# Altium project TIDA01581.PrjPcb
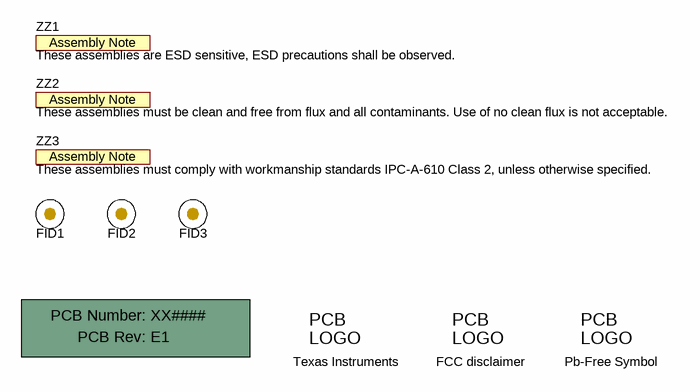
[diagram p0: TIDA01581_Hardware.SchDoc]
CopyrightYear: 2016; PCB_Layout: Garrett Satterfield; PCB_Rev: E1; PRJ_Customer: Public Release; PRJ_Engineer: Garrett Satterfield; PRJ_Number: XX####; PRJ_Title: TIDA-01581; SCH_Rev: E1; TechSupport: http://www.ti.com/support; TID: N/A
3 sheets, 135 parts. Net scope: flat (ports and power ports of the same name join across sheets).
Board file: TIDA01581.PcbDoc
Sheets:
  TIDA01581_Hardware.SchDoc
  TIDA01581_1.SchDoc
  TIDA01581_2.SchDoc

## Sheet TIDA01581_Hardware.SchDoc: Hardware
size 431 x 279 mm; Date: Not shown in title block; ApprovedBy: Not shown in title block; CheckedBy: Not shown in title block; Author: Not shown in title block; CompanyName: Not shown in title block; Engineer: Not shown in title block; Organization: Not shown in title block; Address1: Not shown in title block; Address2: Not shown in title block; Address3: Not shown in title block; Address4: Not shown in title block; DocumentNumber: 1; Revision: Use project parameter SCH_Rev; SheetNumber: 2; SheetTotal: 2; PageSetup: Record=PageOptions¦CenterHorizontal=True¦CenterVertical=True¦PrintScale=1.00¦XCorrection=1.00¦YCorrection=1.00¦PrintKind=0¦BorderSize=5000000¦LeftOffset=0¦BottomOffset=0¦Orientation=2¦PaperLength=1000¦PaperWidth=1000¦Scale=100¦PaperSource=15¦PrintQuality=600¦MediaType=1¦DitherType=10¦PaperKind=Letter¦PrintScaleMode=1

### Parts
!PCB1  Printed Circuit Board  (value not drawn)  (mechanical)
FID1  Fiducial  [Fiducial10-20]  (value not drawn)
FID2  Fiducial  [Fiducial10-20]  (value not drawn)
FID3  Fiducial  [Fiducial10-20]  (value not drawn)
Logo1  Texas Instruments  [TI_Stacked_Overlay_Small]  (no BOM)
Logo2  FCC disclaimer  [FCC_disclaimer]  (no BOM)
Logo3  Pb-Free Symbol  [Pb-Free_Overlay_Small]  (no BOM)
ZZ1  These assemblies are ESD sensitive, ESD precautions shall be observed.  [AssemblyNote]  (no BOM)
ZZ2  These assemblies must be clean and free from flux and all contaminants. Use of no clean flux is not acceptable.  [AssemblyNote]  (no BOM)
ZZ3  These assemblies must comply with workmanship standards IPC-A-610 Class 2, unless otherwise specified.  [AssemblyNote]  (no BOM)

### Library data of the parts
!PCB1 = PCB: Manufacturer: Any; PartNumber: XX####; SymbolCreator: a0412235
FID1-FID3 = Fiducial: Fiducial mark.  There is nothing to buy or mount.; SymbolCreator: codlsc
Logo1 = TI_Logo: Texas Instrument Corporate Signature; SymbolCreator: codlsc
Logo2 = FCC_disclaimer: SymbolCreator: a0412235
Logo3 = Pb-Free: SymbolCreator: a0412235
ZZ1-ZZ3 = AssemblyNote: SymbolCreator: codlsc

## Sheet TIDA01581_1.SchDoc: Boost LED Driver
size 431 x 279 mm; Date: Not shown in title block; ApprovedBy: Not shown in title block; CheckedBy: Not shown in title block; Author: Not shown in title block; CompanyName: Not shown in title block; DrawnBy: Garrett Satterfield; Engineer: Not shown in title block; Organization: Not shown in title block; Address1: Not shown in title block; Address2: Not shown in title block; Address3: Not shown in title block; Address4: Not shown in title block; DocumentNumber: 1; Revision: Use project parameter SCH_Rev; SheetNumber: 1; SheetTotal: 2; PageSetup: Record=PageOptions¦CenterHorizontal=True¦CenterVertical=True¦PrintScale=0.64¦XCorrection=1.00¦YCorrection=1.00¦PrintKind=0¦BorderSize=5000000¦LeftOffset=0¦BottomOffset=0¦Orientation=2¦PaperLength=1000¦PaperWidth=1000¦Scale=100¦PaperSource=15¦PrintQuality=-3¦MediaType=1¦DitherType=10¦PrintScaleMode=1¦PaperKind=Letter¦PaperIndex=1
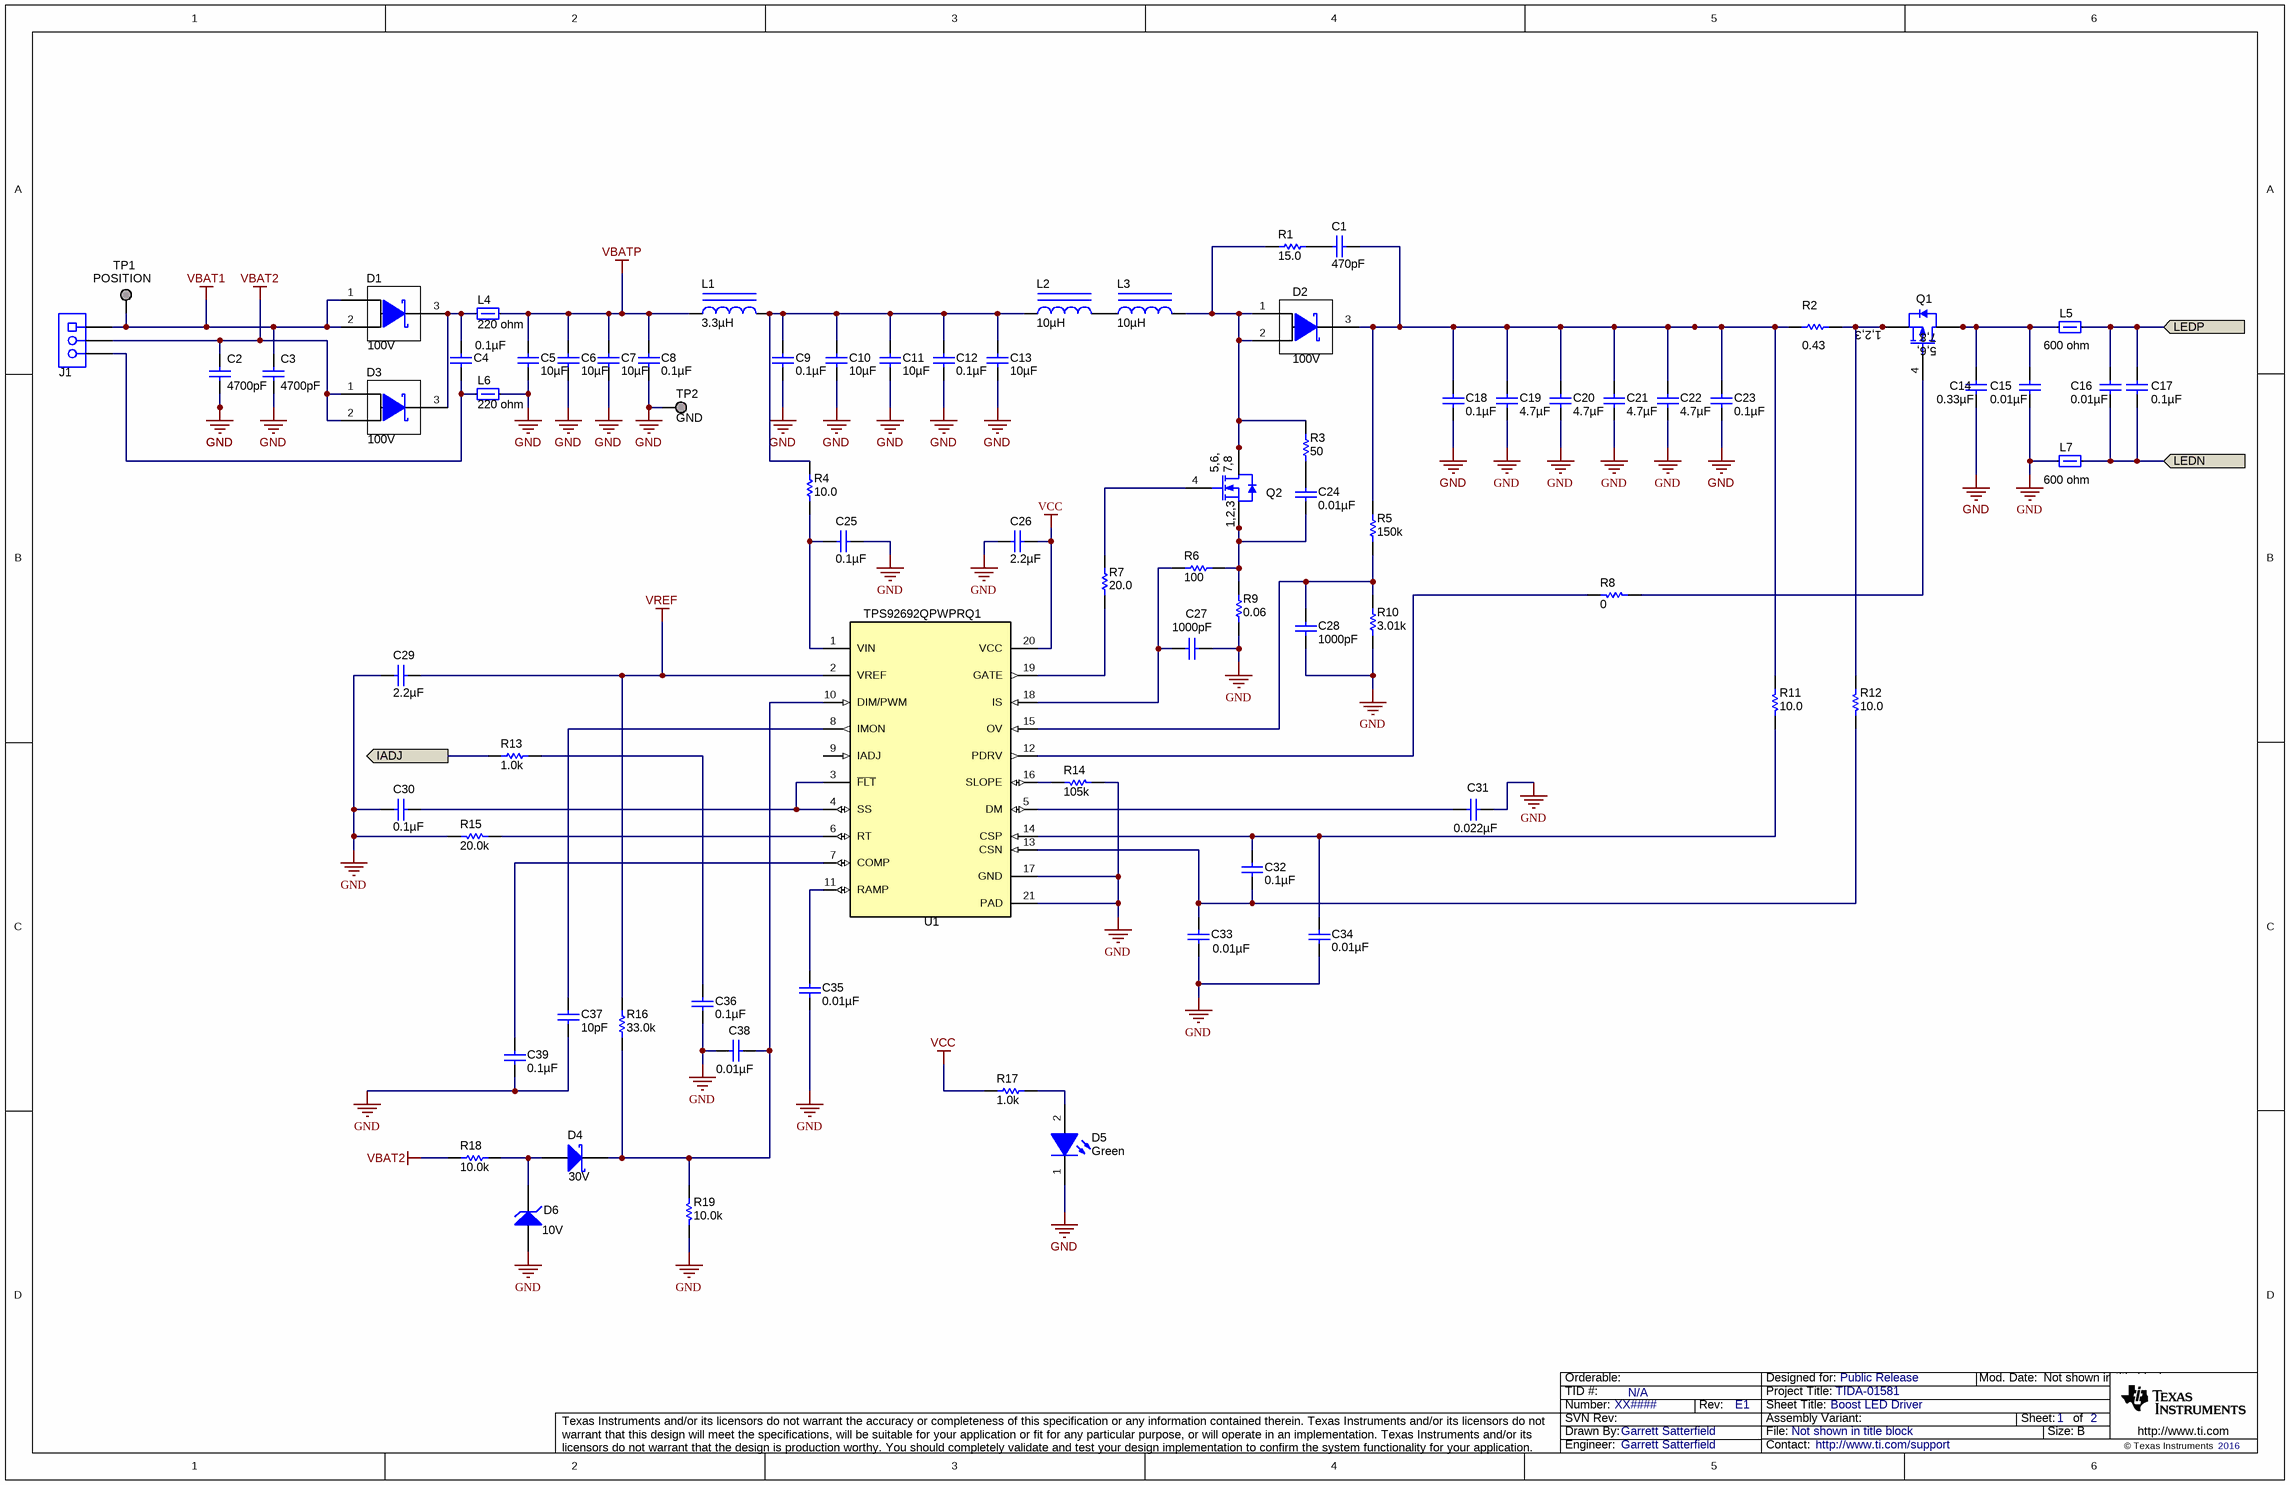
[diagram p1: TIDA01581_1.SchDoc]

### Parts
C1  ValueDisplayed: 470pF  [0603]  (hidden comment: GRM188R72A471KA01D)
C2  ValueDisplayed: 4700pF  [0603_HV]  (hidden comment: CGA3E2X7R2A472K080AA)
C3  ValueDisplayed: 4700pF  [0603_HV]  (hidden comment: CGA3E2X7R2A472K080AA)
C4  ValueDisplayed: 0.1µF  [0603_HV]  (hidden comment: CGA3E2X7R1H104K080AA)
C5  ValueDisplayed: 10µF  [1210_280]  (hidden comment: CGA6P3X7S1H106K250AB)
C6  ValueDisplayed: 10µF  [1210_280]  (hidden comment: CGA6P3X7S1H106K250AB)
C7  ValueDisplayed: 10µF  [1210_280]  (hidden comment: CGA6P3X7S1H106K250AB)
C8  ValueDisplayed: 0.1µF  [0603_HV]  (hidden comment: CGA3E2X7R1H104K080AA)
C9  ValueDisplayed: 0.1µF  [0603_HV]  (hidden comment: CGA3E2X7R1H104K080AA)
C10  ValueDisplayed: 10µF  [1210_280]  (hidden comment: CGA6P3X7S1H106K250AB)
C11  ValueDisplayed: 10µF  [1210_280]  (hidden comment: CGA6P3X7S1H106K250AB)
C12  ValueDisplayed: 0.1µF  [0603_HV]  (hidden comment: CGA3E2X7R1H104K080AA)
C13  ValueDisplayed: 10µF  [1210_280]  (hidden comment: CGA6P3X7S1H106K250AB)
C14  ValueDisplayed: 0.33µF  [0805_HV]  (hidden comment: C2012X7S2A334K125AB)
C15  ValueDisplayed: 0.01µF  [0603]  (hidden comment: CGA3E2X7R2A103K080AA)
C16  ValueDisplayed: 0.01µF  [0603_HV]  (hidden comment: CGA3E2X7R2A103K080AA)
C17  ValueDisplayed: 0.1µF  [0603_HV]  (hidden comment: CGA3E2X7R1H104K080AA)
C18  ValueDisplayed: 0.1µF  [0603_HV]  (hidden comment: CGA3E2X7R1H104K080AA)
C19  ValueDisplayed: 4.7µF  [1210_220]  (hidden comment: CGA6M3X7S2A475K200AB)
C20  ValueDisplayed: 4.7µF  [1210_220]  (hidden comment: CGA6M3X7S2A475K200AB)
C21  ValueDisplayed: 4.7µF  [1210_220]  (hidden comment: CGA6M3X7S2A475K200AB)
C22  ValueDisplayed: 4.7µF  [1210_220]  (hidden comment: CGA6M3X7S2A475K200AB)
C23  ValueDisplayed: 0.1µF  [0603_HV]  (hidden comment: CGA3E2X7R1H104K080AA)
C24  ValueDisplayed: 0.01µF  [0603]  (hidden comment: 06031C103MAT2A)
C25  ValueDisplayed: 0.1µF  [0805_HV]  (hidden comment: C2012X7R2A104K125AA)
C26  ValueDisplayed: 2.2µF  [0805_HV]  (hidden comment: CGA4J3X7R1E225K125AB)
C27  ValueDisplayed: 1000pF  [0603_HV]  (hidden comment: CGA3E2X7R2A102K080AA)
C28  ValueDisplayed: 1000pF  [0603]  (hidden comment: CGA3E2X7R2A102K080AA)
C29  ValueDisplayed: 2.2µF  [0805_HV]  (hidden comment: CGA4J3X7R1E225K125AB)
C30  ValueDisplayed: 0.1µF  [1206_180]  (hidden comment: CGA5L2X7R2A104K160AA)
C31  ValueDisplayed: 0.022µF  [0603_HV]  (hidden comment: CGA3E2X7R2A223K080AA)
C32  ValueDisplayed: 0.1µF  [1206_180]  (hidden comment: CGA5L2X7R2A104K160AA)
C33  ValueDisplayed: 0.01µF  [0603]  (hidden comment: CGA3E2X7R2A103K080AA)
C34  ValueDisplayed: 0.01µF  [0603_HV]  (hidden comment: CGA3E2X7R2A103K080AA)
C35  ValueDisplayed: 0.01µF  [0603]  (hidden comment: CGA3E2X7R2A103K080AA)
C36  ValueDisplayed: 0.1µF  [1206_180]  (hidden comment: CGA5L2X7R2A104K160AA)
C37  ValueDisplayed: 10pF  [0603_HV]  (hidden comment: CGA3E2C0G1H100D080AA)
C38  ValueDisplayed: 0.01µF  [0603_HV]  (hidden comment: CGA3E2X7R2A103K080AA)
C39  ValueDisplayed: 0.1µF  [0805_HV]  (hidden comment: CEU4J2X7R1H104K125AE)
D1  value 100V  [TO-277A]  (hidden comment: V12P10-M3/86A)
D2  value 100V  [PowerDI5]  (hidden comment: PDS3100Q-13)
D3  value 100V  [TO-277A]  (hidden comment: V12P10-M3/86A)
D4  value 30V  [SOD-123]  (hidden comment: BAT42W-7-F)
D5  value Green  [WL-SMCW_GREEN]  (hidden comment: 150060VS75000)
D6  value 10V  [SOD-123]  (hidden comment: MMSZ5240B-7-F)
J1  1727023  [Phoenix_1727023]  (value not drawn)
L1  ValueDisplayed: 3.3µH  [CLF7045]  (hidden comment: CLF7045T-3R3N)
L2  ValueDisplayed: 10µH  [IHLP-2525BD]  (hidden comment: IHLP2525BDER100M01)
L3  ValueDisplayed: 10µH  [IHLP-2525BD]  (hidden comment: IHLP2525BDER100M01)
L4  value 220 ohm  [1206]  (hidden comment: FBMH3216HM221NTV)
L5  value 600 ohm  [1206]  (hidden comment: MI1206K601R-10)
L6  value 220 ohm  [1206]  (hidden comment: FBMH3216HM221NTV)
L7  value 600 ohm  [1206]  (hidden comment: MI1206K601R-10)
Q1  SI7415DN-T1-GE3  [PowerPAK_1212-8]  (value not drawn)
Q2  STL8N10LF3  [PowerFLAT5x6_R]  (value not drawn)
R1  ValueDisplayed: 15.0  [0603]  (hidden comment: CRCW060315R0FKEA)
R2  0.43  [1206]
R3  ValueDisplayed: 50  [0603]  (hidden comment: CRCW060350R0FKEA)
R4  ValueDisplayed: 10.0  [1206]  (hidden comment: CRCW120610R0FKEA)
R5  ValueDisplayed: 150k  [0603_HV]  (hidden comment: CRCW0603150KFKEA)
R6  ValueDisplayed: 100  [0603_HV]  (hidden comment: CRCW0603100RFKEA)
R7  ValueDisplayed: 20.0  [0603]  (hidden comment: CRCW060320R0FKEA)
R8  ValueDisplayed: 0  [0603_HV]  (hidden comment: CRCW06030000Z0EA)
R9  ValueDisplayed: 0.06  [2010]  (hidden comment: CSRN2010FK60L0)
R10  ValueDisplayed: 3.01k  [0603_HV]  (hidden comment: CRCW06033K01FKEA)
R11  ValueDisplayed: 10.0  [0603_HV]  (hidden comment: CRCW060310R0FKEA)
R12  ValueDisplayed: 10.0  [0603_HV]  (hidden comment: CRCW060310R0FKEA)
R13  ValueDisplayed: 1.0k  [0603]  (hidden comment: CRCW06031K00JNEA)
R14  ValueDisplayed: 105k  [0603_HV]  (hidden comment: CRCW0603105KFKEA)
R15  ValueDisplayed: 20.0k  [0603_HV]  (hidden comment: CRCW060320K0FKEA)
R16  ValueDisplayed: 33.0k  [0603]  (hidden comment: CRCW060333K0FKEA)
R17  ValueDisplayed: 1.0k  [0603]  (hidden comment: CRCW06031K00JNEA)
R18  ValueDisplayed: 10.0k  [0603_HV]  (hidden comment: CRCW060310K0FKEA)
R19  ValueDisplayed: 10.0k  [0603]  (hidden comment: CRCW060310K0FKEA)
TP1  POSITION  [Keystone1502-2]
TP2  GND  [Keystone1502-2]
U1  TPS92692QPWPRQ1  [PWP0020D_N]

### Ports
IADJ, LEDN, LEDP

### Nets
GND: C2.2 C3.2 C5.2 C6.2 C7.2 C8.2 C9.2 C10.2 C11.2 C12.2 C13.2 C14.2 C15.2 C18.2 C19.1 C20.1 C21.1 C22.1 C23.2 C25.1 C26.2 C27.2 C28.2 C29.1 C30.1 C31.1 C33.2 C34.2 C35.2 C36.2 C37.2 C38.2 C39.1 D5.1(K) D6.2(A) L6.2 L7.1 R9.1 R10.1 R14.1 R15.2 R19.1 TP2.1 U1.17(GND) U1.21(PAD)
VBAT1: C3.1 D1.1(A) D1.2(A) J1.1 TP1.1
VBAT2: C2.1 D3.1(A) D3.2(A) J1.2 R18.2
VBATP: C5.1 C6.1 C7.1 C8.1 L1.1 L4.2
VCC: C26.1 R17.1 U1.20(VCC)
VREF: C29.2 R16.1 U1.2(VREF)
IADJ: R13.1 ; port IADJ
LEDN: C16.1 C17.2 L7.2 ; port LEDN
LEDP: C16.2 C17.1 L5.2 ; port LEDP
NetC1_1: C1.1 C18.1 C19.2 C20.2 C21.2 C22.2 C23.1 D2.3(K) R2.1 R5.2 R11.2
NetC1_2: C1.2 R1.2
NetC4_1: C4.1 D1.3(K) D3.3(K) L4.1
NetC4_2: C4.2 J1.3 L6.1
NetC9_1: C9.1 C10.1 C11.1 C12.1 C13.1 L1.2 L2.1 R4.2
NetC14_1: C14.1 C15.1 L5.1 Q1.5(D) Q1.6(D) Q1.7(D) Q1.8(D) Q1.9(D)
NetC24_1: C24.1 R3.1
NetC24_2: C24.2 Q2.1(S) Q2.2(S) Q2.3(S) R6.2 R9.2
NetC25_2: C25.2 R4.1 U1.1(VIN)
NetC27_1: C27.1 R6.1 U1.18(IS)
NetC28_1: C28.1 R5.1 R10.2 U1.15(OV)
NetC30_2: C30.2 U1.3(~{FLT}) U1.4(SS)
NetC31_2: C31.2 U1.5(DM)
NetC32_1: C32.1 C34.1 R11.1 U1.14(CSP)
NetC32_2: C32.2 C33.1 R12.1 U1.13(CSN)
NetC35_1: C35.1 U1.11(RAMP)
NetC36_1: C36.1 R13.2
NetC37_1: C37.1 U1.8(IMON)
NetC38_1: C38.1 D4.1(K) R16.2 R19.2 U1.10(DIM/PWM)
NetC39_2: C39.2 U1.7(COMP)
NetD2_1: D2.1(A) D2.2(A) L3.2 Q2.5(D) Q2.6(D) Q2.7(D) Q2.8(D) Q2.9(D) R1.1 R3.2
NetD4_2: D4.2(A) D6.1(K) R18.1
NetD5_2: D5.2(A) R17.2
NetL2_2: L2.2 L3.1
NetQ1_1: Q1.1(S) Q1.2(S) Q1.3(S) R2.2 R12.2
NetQ1_4: Q1.4(G) R8.1
NetQ2_4: Q2.4(G) R7.2
NetR7_1: R7.1 U1.19(GATE)
NetR8_2: R8.2 U1.12(PDRV)
NetR14_2: R14.2 U1.16(SLOPE)
NetR15_1: R15.1 U1.6(RT)

Not connected (* = marked no-connect by the designer): U1 9(IADJ)

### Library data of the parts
C1 = GRM188R72A471KA01D: CAP, CERM, 470 pF, 100 V, +/- 10%, X7R, 0603; Manufacturer: MuRata; Polarized: N; CompType: Capacitor; Value: 470pF; U/M: EA; Cap_F: 0.00000000047; Tolerance_%: 10; Value1: Unknown; VDC_V: 100; Value2: 100V; TaMin_C: -55; TaMax_C: 125; SizeArea_mm2: 1.28; SizeAreaWB_mm2: 4.68; SizeX_mm: 1.6; SizeY_mm: 0.8; SizeZ_mm: 1; AEC Category: Q200
C2 C3 = CGA3E2X7R2A472K080AA: CAP, CERM, 4700 pF, 100 V, +/- 10%, X7R, AEC-Q200 Grade 1, 0603; Manufacturer: TDK; Polarized: N; CompType: Capacitor; Value: 4700pF; U/M: EA; Cap_F: 0.0000000047; Tolerance_%: 10; ESR_ohm: 0.469862; Value1: 0.469862 ohm; VDC_V: 100; Value2: 100V; IRMS_A: 0.32335; TaMin_C: -55; TaMax_C: 125; Cap_Case: 0603; SizeArea_mm2: 1.28; SizeAreaWB_mm2: 4.68; SizeX_mm: 1.6; SizeY_mm: 0.8; SizeZ_mm: 1; AEC Category: Q200; AEC Qualified: Y
C4 C8 C9 C12 C17 C18 C23 = CGA3E2X7R1H104K080AA: CAP, CERM, 0.1 µF, 50 V, +/- 10%, X7R, AEC-Q200 Grade 1, 0603; Manufacturer: TDK; Polarized: N; CompType: Capacitor; Value: 0.1uF; U/M: EA; Cap_F: 0.0000001; Tolerance_%: 10; ESR_ohm: 0.0296; Value1: 0.0296 ohm; VDC_V: 50; Value2: 50V; IRMS_A: 0.97199; TaMin_C: -55; TaMax_C: 125; Cap_Case: 0603; SizeArea_mm2: 1.28; SizeAreaWB_mm2: 4.68; SizeX_mm: 1.6; SizeY_mm: 0.8; SizeZ_mm: 1; AEC Category: Q200; AEC Qualified: Y
C5-C7 C10 C11 C13 = CGA6P3X7S1H106K250AB: CAP, CERM, 10 µF, 50 V, +/- 10%, X7S, AEC-Q200 Grade 1, 1210; Manufacturer: TDK; Polarized: N; CompType: Capacitor; Value: 10uF; U/M: EA; Cap_F: 0.00001; Tolerance_%: 10; ESR_ohm: 0.002827; Value1: 0.002827 ohm; VDC_V: 50; Value2: 50V; IRMS_A: 4.37286; TaMin_C: -55; TaMax_C: 125; SizeArea_mm2: 8; SizeAreaWB_mm2: 14.7; SizeX_mm: 3.2; SizeY_mm: 2.5; SizeZ_mm: 2.8; AEC Category: Q200; AEC Qualified: Y; AEC Grade: 1
C14 = C2012X7S2A334K125AB: CAP, CERM, 0.33 µF, 100 V, +/- 10%, X7S, 0805; Manufacturer: TDK; Polarized: N; CompType: Capacitor; Value: 0.33uF; U/M: EA; Cap_F: 0.00000033; Tolerance_%: 10; ESR_ohm: 0.019477; Value1: 0.019477 ohm; VDC_V: 100; Value2: 100V; IRMS_A: 1.48561; TaMin_C: -55; TaMax_C: 125; Cap_Case: 0805; SizeArea_mm2: 2.5; SizeAreaWB_mm2: 6.75; SizeX_mm: 2; SizeY_mm: 1.25; SizeZ_mm: 1.45; AEC Category: Q200
C15 C33 C35 = CGA3E2X7R2A103K080AA: CAP, CERM, 0.01 µF, 100 V, +/- 10%, X7R, AEC-Q200 Grade 1, 0603; Manufacturer: TDK; Polarized: N; CompType: Capacitor; Value: 0.01uF; U/M: EA; Cap_F: 0.00000001; Tolerance_%: 10; ESR_ohm: 0.235428; Value1: 0.235428 ohm; VDC_V: 100; Value2: 100V; IRMS_A: 0.396995; TaMin_C: -55; TaMax_C: 125; SizeArea_mm2: 1.28; SizeAreaWB_mm2: 4.68; SizeX_mm: 1.6; SizeY_mm: 0.8; SizeZ_mm: 1; AEC Category: Q200; AEC Qualified: Y
C16 C34 C38 = CGA3E2X7R2A103K080AA: CAP, CERM, 0.01 µF, 100 V, +/- 10%, X7R, AEC-Q200 Grade 1, 0603; Manufacturer: TDK; Polarized: N; CompType: Capacitor; Value: 0.01uF; U/M: EA; Cap_F: 0.00000001; Tolerance_%: 10; ESR_ohm: 0.235428; Value1: 0.235428 ohm; VDC_V: 100; Value2: 100V; IRMS_A: 0.396995; TaMin_C: -55; TaMax_C: 125; Cap_Case: 0603; SizeArea_mm2: 1.28; SizeAreaWB_mm2: 4.68; SizeX_mm: 1.6; SizeY_mm: 0.8; SizeZ_mm: 1; AEC Category: Q200; AEC Qualified: Y
C19-C22 = CGA6M3X7S2A475K200AB: CAP, CERM, 4.7 µF, 100 V, +/- 10%, X7S, AEC-Q200 Grade 1, 1210; Manufacturer: TDK; Polarized: N; CompType: Capacitor; Value: 4.7uF; U/M: EA; Cap_F: 0.0000047; Tolerance_%: 10; ESR_ohm: 0.004236; Value1: 0.004236 ohm; VDC_V: 100; Value2: 100V; IRMS_A: 3.57337; TaMin_C: -55; TaMax_C: 125; SizeArea_mm2: 8; SizeAreaWB_mm2: 14.7; SizeX_mm: 3.2; SizeY_mm: 2.5; SizeZ_mm: 2.2; AEC Category: Q200; AEC Qualified: Y; AEC Grade: 1
C24 = 06031C103MAT2A: CAP, CERM, 0.01 µF, 100 V, +/- 20%, X7R, 0603; Manufacturer: AVX; Polarized: N; CompType: Capacitor; Value: 0.01uF; U/M: EA; Cap_F: 0.00000001; Tolerance_%: 20; ESR_ohm: 0.098; Value1: 0.098 ohm; VDC_V: 100; Value2: 100V; TaMin_C: -55; TaMax_C: 125; SizeArea_mm2: 1.28; SizeAreaWB_mm2: 4.68; SizeX_mm: 1.6; SizeY_mm: 0.8; SizeZ_mm: 1; AEC Category: Q200
C25 = C2012X7R2A104K125AA: CAP, CERM, 0.1 µF, 100 V, +/- 10%, X7R, 0805; Manufacturer: TDK; Polarized: N; CompType: Capacitor; Value: 0.1uF; U/M: EA; Cap_F: 0.0000001; Tolerance_%: 10; ESR_ohm: 0.0158; Value1: 0.0158 ohm; VDC_V: 100; Value2: 100V; TaMin_C: -55; TaMax_C: 125; Cap_Case: 0805; AEC Category: Q200
C26 C29 = CGA4J3X7R1E225K125AB: CAP, CERM, 2.2 µF, 25 V, +/- 10%, X7R, AEC-Q200 Grade 1, 0805; Manufacturer: TDK; Polarized: N; CompType: Capacitor; Value: 2.2uF; U/M: EA; Cap_F: 0.0000022; Tolerance_%: 10; Value1: Unknown; VDC_V: 25; Value2: 25V; TaMin_C: -55; TaMax_C: 125; Cap_Case: 0805; SizeArea_mm2: 2.5; SizeAreaWB_mm2: 6.75; SizeX_mm: 2; SizeY_mm: 1.25; SizeZ_mm: 1.45; AEC Category: Q200; AEC Qualified: Y; AEC Grade: 1
C27 = CGA3E2X7R2A102K080AA: CAP, CERM, 1000 pF, 100 V, +/- 10%, X7R, AEC-Q200 Grade 1, 0603; Manufacturer: TDK; Polarized: N; CompType: Capacitor; Value: 1000pF; U/M: EA; Cap_F: 0.000000001; Tolerance_%: 10; ESR_ohm: 1.97137; Value1: 1.97137 ohm; VDC_V: 100; Value2: 100V; IRMS_A: 0.305705; TaMin_C: -55; TaMax_C: 125; Cap_Case: 0603; SizeArea_mm2: 1.28; SizeAreaWB_mm2: 4.68; SizeX_mm: 1.6; SizeY_mm: 0.8; SizeZ_mm: 1; AEC Category: Q200; AEC Qualified: Y
C28 = CGA3E2X7R2A102K080AA: CAP, CERM, 1000 pF, 100 V, +/- 10%, X7R, AEC-Q200 Grade 1, 0603; Manufacturer: TDK; Polarized: N; CompType: Capacitor; Value: 1000pF; U/M: EA; Cap_F: 0.000000001; Tolerance_%: 10; ESR_ohm: 1.97137; Value1: 1.97137 ohm; VDC_V: 100; Value2: 100V; IRMS_A: 0.305705; TaMin_C: -55; TaMax_C: 125; SizeArea_mm2: 1.28; SizeAreaWB_mm2: 4.68; SizeX_mm: 1.6; SizeY_mm: 0.8; SizeZ_mm: 1; AEC Category: Q200; AEC Qualified: Y
C30 C32 C36 = CGA5L2X7R2A104K160AA: CAP, CERM, 0.1 µF, 100 V, +/- 10%, X7R, AEC-Q200 Grade 1, 1206; Manufacturer: TDK; Polarized: N; CompType: Capacitor; Value: 0.1uF; U/M: EA; Cap_F: 0.0000001; Tolerance_%: 10; ESR_ohm: 0.030343; Value1: 0.030343 ohm; VDC_V: 100; Value2: 100V; IRMS_A: 1.33802; TaMin_C: -55; TaMax_C: 125; SizeArea_mm2: 5.12; SizeAreaWB_mm2: 10.92; SizeX_mm: 3.2; SizeY_mm: 1.6; SizeZ_mm: 1.8; AEC Category: Q200; AEC Qualified: Y; AEC Grade: 1
C31 = CGA3E2X7R2A223K080AA: CAP, CERM, 0.022 µF, 100 V, +/- 10%, X7R, AEC-Q200 Grade 1, 0603; Manufacturer: TDK; Polarized: N; CompType: Capacitor; Value: 0.022uF; U/M: EA; Cap_F: 0.000000022; Tolerance_%: 10; ESR_ohm: 0.083542; Value1: 0.083542 ohm; VDC_V: 100; Value2: 100V; IRMS_A: 0.609312; TaMin_C: -55; TaMax_C: 125; Cap_Case: 0603; SizeArea_mm2: 1.28; SizeAreaWB_mm2: 4.68; SizeX_mm: 1.6; SizeY_mm: 0.8; SizeZ_mm: 1; AEC Category: Q200; AEC Qualified: Y
C37 = CGA3E2C0G1H100D080AA: CAP, CERM, 10 pF, 50 V, +/- 5%, C0G/NP0, AEC-Q200 Grade 1, 0603; Manufacturer: TDK; Polarized: N; CompType: Capacitor; Value: 10pF; U/M: EA; Cap_F: 0.00000000001; Tolerance_%: 5; Value1: Unknown; VDC_V: 50; Value2: 50V; TaMin_C: -55; TaMax_C: 125; Cap_Case: 0603; SizeArea_mm2: 1.28; SizeAreaWB_mm2: 4.68; SizeX_mm: 1.6; SizeY_mm: 0.8; SizeZ_mm: 1; AEC Category: Q200; AEC Qualified: Y
C39 = CEU4J2X7R1H104K125AE: CAP, CERM, 0.1 µF, 50 V, +/- 10%, X7R, AEC-Q200 Grade 1, 0805; Manufacturer: TDK; Polarized: N; CompType: Capacitor; Value: 0.1uF; U/M: EA; Cap_F: 0.0000001; Tolerance_%: 10; Value1: Unknown; VDC_V: 50; Value2: 50V; TaMin_C: -55; TaMax_C: 125; Cap_Case: 0805; SizeArea_mm2: 2.5; SizeAreaWB_mm2: 6.75; SizeX_mm: 2; SizeY_mm: 1.25; SizeZ_mm: 1.5; AEC Category: Q200; AEC Qualified: Y; AEC Grade: 1
D1 D3 = V12P10-M3/86A: Diode, Schottky, 100 V, 12 A, AEC-Q101, TO-277A; Manufacturer: Vishay-Semiconductor; U/M: EA; Vf_V: 0.7; Value1: 12A; Value2: 0.7V; Io_A: 12; Vr_V: 100; TJmax_C: 150; SizeAreaWB_mm2: 56.1; SizeArea_mm2: 29.9; SizeX_mm: 4.6; SizeY_mm: 6.5; SizeZ_mm: 1.2; AEC Category: Q101; AEC Qualified: Y
D2 = PDS3100Q-13: Diode, Schottky, 100 V, 3 A, AEC-Q101, PowerDI5; Manufacturer: Diodes Inc.; U/M: EA; Vf_V: 0.76; Value1: 3A; Value2: 0.76V; Io_A: 3; Vr_V: 100; TJmax_C: 150; AEC Category: Q101; AEC Qualified: Y
D4 = BAT42W-7-F: Diode, Schottky, 30 V, 0.2 A, SOD-123; Manufacturer: Diodes Inc.; U/M: EA; Vf_V: 1; Value1: 0.2A; Value2: 1V; Io_A: 0.2; Vr_V: 30; AEC Category: Q101
D5 = 150060VS75000: LED, Green, SMD; Manufacturer: Wurth Elektronik; Type: AlInGaP; Vf_V: 2; Value2: 2V; Io_A: 0.02; Value1: W; U/M: EA
D6 = MMSZ5240B-7-F: Diode, Zener, 10 V, 500 mW, SOD-123; Manufacturer: Diodes Inc.; SymbolCreator: a0412235; U/M: EA; Power_W: 0.5; Vz_V: 10; Value1: 0.5W; RJA_CperW: 350; SizeAreaWB_mm2: 13.095; SizeArea_mm2: 6.545; SizeX_mm: 3.85; SizeY_mm: 1.7; SizeZ_mm: 1.35; AEC Category: Q101
J1 = 1727023: Terminal Block Receptacle, 3x1, 3.81mm, R/A, TH; Manufacturer: Phoenix Contact; SymbolCreator: a0412235
L1 = CLF7045T-3R3N: Inductor, Shielded, Ferrite, 3.3 µH, 5 A, 0.0213 ohm, SMD; Manufacturer: TDK; Value: 3.3uH; Ind_H: 3.3E-6; Imax_A: 5; Irms: 4.1A @ 30C rise; Isat: 5A @ 10% inductance drop; DCR_ohm: 0.0213; Value2: 5A; SizeAreaWB_mm2: 85.54; SizeArea_mm2: 52.54; SizeX_mm: 7.4; SizeY_mm: 7.1; SizeZ_mm: 4.8; AEC Category: Q200
L2 L3 = IHLP2525BDER100M01: Inductor, Shielded, Powdered Iron, 10 µH, 2.5 A, 0.129 ohm, SMD; Manufacturer: Vishay-Dale; Value: 10uH; Ind_H: 10.0E-6; Imax_A: 2.5; Irms: 2.5A @ 40C rise; Isat: 7A @ 20% inductance drop; DCR_ohm: 0.129; Value2: 2.5A; SizeAreaWB_mm2: 75.0442; SizeArea_mm2: 44.3842; SizeX_mm: 6.86; SizeY_mm: 6.47; SizeZ_mm: 2.4; AEC Category: Q200
L4 L6 = FBMH3216HM221NTV: Ferrite Bead, 220 ohm @ 100 MHz, 4 A, 1206; Manufacturer: Taiyo Yuden; Imax_A: 4; DCR_ohm: 0.02; Value1: 0.02 ohm; Value2: 4A; SizeAreaWB_mm2: 10.92; SizeArea_mm2: 5.12; SizeX_mm: 3.2; SizeY_mm: 1.6; SizeZ_mm: 1.35; ZTyp@100MHz_Ohm: 220
L5 L7 = MI1206K601R-10: Ferrite Bead, 600 ohm @ 100 MHz, 1.5 A, 1206; Manufacturer: Laird-Signal Integrity Products; Imax_A: 1.5; DCR_ohm: 0.08; Value1: 0.08 ohm; Value2: 1.5A; ZTyp@100MHz_Ohm: 600; Ztyp@1GHz_Ohm: 130
Q1 = SI7415DN-T1-GE3: MOSFET, P-CH, -60 V, -3.6 A, PowerPAK 1212; Manufacturer: Vishay-Siliconix; Alternate Manufacturer: None; U/M: EA; ChType: P; Value: -60V; Value1: 0.11 ohm; Rdson45_ohm: 0.11; Value2: 15 nC; QgTyp_nC: 15; Vgs_V: 20
Q2 = STL8N10LF3: MOSFET, N-CH, 100 V, 20 A, AEC-Q101, 8-PowerVDFN; Manufacturer: STMicroelectronics; Alternate Manufacturer: None; U/M: EA; ChType: N; Value: 100V; VdsMax_V: 100; Value1: ? ohm; Value2: 20.5 nC; QgTyp_nC: 20.5; Vgs_V: 20; AEC Category: Q101; AEC Qualified: Y
R1 = CRCW060315R0FKEA: RES, 15.0, 1%, 0.1 W, 0603; Manufacturer: Vishay-Dale; CompType: Resistor; Value: 15.0; Res_ohm: 15; Value_Code: 15R0; Tolerance_%: 1; Power_W: 0.1; Value2: 0.1W; VDC_V: 75; TempCo: 100 ppm/C; SizeArea_mm2: 1.28; SizeX_mm: 1.6; SizeY_mm: 0.8; EIA_Code: E96; U/M: EA; AEC Category: Q200
R2 = CMP-0078337-1: RES, 0.43, 1%, 0.5 W, 1206
R3 = CRCW060350R0FKEA: RES, 50, 1%, 0.1 W, 0603; Manufacturer: Vishay-Dale; CompType: Resistor; Value: 50; Value_Code: 50R0; Tolerance_%: 1; Power_W: 0.1; Value2: 0.1W; VDC_V: 75; TempCo: 100 ppm/C; SizeArea_mm2: 1.28; SizeX_mm: 1.6; SizeY_mm: 0.8; U/M: EA; AEC Category: Q200
R4 = CRCW120610R0FKEA: RES, 10.0, 1%, 0.25 W, 1206; Manufacturer: Vishay-Dale; CompType: Resistor; Value: 10.0; Res_ohm: 10; Value_Code: 10R0; Tolerance_%: 1; Power_W: 0.25; Value2: 0.25W; VDC_V: 200; TempCo: 100 ppm/C; EIA_Code: E96; U/M: EA
R5 = CRCW0603150KFKEA: RES, 150 k, 1%, 0.1 W, 0603; Manufacturer: Vishay-Dale; CompType: Resistor; Value: 150k; Res_ohm: 150000; Tolerance_%: 1; Power_W: 0.1; Value2: 0.1W; VDC_V: 75; TempCo: 100 ppm/C; SizeArea_mm2: 1.28; SizeX_mm: 1.6; SizeY_mm: 0.8; EIA_Code: E96; U/M: EA; AEC Category: Q200
R6 = CRCW0603100RFKEA: RES, 100, 1%, 0.1 W, 0603; Manufacturer: Vishay-Dale; CompType: Resistor; Value: 100; Value_Code: 100R; Tolerance_%: 1; Power_W: 0.1; Value2: 0.1W; VDC_V: 75; TempCo: 100 ppm/C; EIA_Code: E96; U/M: EA; AEC Category: Q200
R7 = CRCW060320R0FKEA: RES, 20.0, 1%, 0.1 W, 0603; Manufacturer: Vishay-Dale; CompType: Resistor; Value: 20.0; Res_ohm: 20; Value_Code: 20R0; Tolerance_%: 1; Power_W: 0.1; Value2: 0.1W; VDC_V: 75; TempCo: 100 ppm/C; SizeArea_mm2: 1.28; SizeX_mm: 1.6; SizeY_mm: 0.8; EIA_Code: E96; U/M: EA; AEC Category: Q200
R8 = CRCW06030000Z0EA: RES, 0, 5%, 0.1 W, 0603; Manufacturer: Vishay-Dale; CompType: Resistor; Value: 0; Value_Code: 0000; Tolerance_%: 5; Power_W: 0.1; Value2: 0.1W; VDC_V: 75; TempCo: 200 ppm/C; EIA_Code: E24; U/M: EA; SizeArea_mm2: 1.28; SizeX_mm: 1.6; SizeY_mm: 0.8; SizeZ_mm: 1; AEC Category: Q200
R9 = CSRN2010FK60L0: RES, 0.06, 1%, 1 W, 2010; Manufacturer: Stackpole Electronics Inc; CompType: Resistor; Value: 0.06; Value_Code: R060; Tolerance_%: 1; Value2: 1W; TempCo: 250 ppm/C; SizeArea_mm2: 12.5; SizeX_mm: 5; SizeY_mm: 2.5; SizeZ_mm: 1.66; U/M: EA; AEC Category: Q200
R10 = CRCW06033K01FKEA: RES, 3.01 k, 1%, 0.1 W, 0603; Manufacturer: Vishay-Dale; CompType: Resistor; Value: 3.01k; Res_ohm: 3010; Value_Code: 3k01; Tolerance_%: 1; Power_W: 0.1; Value2: 0.1W; VDC_V: 75; TempCo: 100 ppm/C; SizeArea_mm2: 1.28; SizeX_mm: 1.6; SizeY_mm: 0.8; EIA_Code: E96; U/M: EA; AEC Category: Q200
R11 R12 = CRCW060310R0FKEA: RES, 10.0, 1%, 0.1 W, 0603; Manufacturer: Vishay-Dale; CompType: Resistor; Value: 10.0; Res_ohm: 10; Value_Code: 10R0; Tolerance_%: 1; Power_W: 0.1; Value2: 0.1W; VDC_V: 75; TempCo: 100 ppm/C; EIA_Code: E96; U/M: EA
R13 R17 = CRCW06031K00JNEA: RES, 1.0 k, 5%, 0.1 W, 0603; Manufacturer: Vishay-Dale; CompType: Resistor; Value: 1.0k; Res_ohm: 1000; Value_Code: 1k00; Tolerance_%: 5; Power_W: 0.1; Value2: 0.1W; VDC_V: 75; TempCo: 200 ppm/C; SizeArea_mm2: 1.28; SizeX_mm: 1.6; SizeY_mm: 0.8; SizeZ_mm: 1; EIA_Code: E24; U/M: EA; AEC Category: Q200
R14 = CRCW0603105KFKEA: RES, 105 k, 1%, 0.1 W, 0603; Manufacturer: Vishay-Dale; CompType: Resistor; Value: 105k; Res_ohm: 105000; Tolerance_%: 1; Power_W: 0.1; Value2: 0.1W; VDC_V: 75; TempCo: 100 ppm/C; SizeArea_mm2: 1.28; SizeX_mm: 1.6; SizeY_mm: 0.8; EIA_Code: E96; U/M: EA; AEC Category: Q200
R15 = CRCW060320K0FKEA: RES, 20.0 k, 1%, 0.1 W, 0603; Manufacturer: Vishay-Dale; CompType: Resistor; Value: 20.0k; Res_ohm: 20000; Value_Code: 20k0; Tolerance_%: 1; Power_W: 0.1; Value2: 0.1W; VDC_V: 75; TempCo: 100 ppm/C; SizeArea_mm2: 1.28; SizeX_mm: 1.6; SizeY_mm: 0.8; EIA_Code: E96; U/M: EA; AEC Category: Q200
R16 = CRCW060333K0FKEA: RES, 33.0 k, 1%, 0.1 W, 0603; Manufacturer: Vishay-Dale; CompType: Resistor; Value: 33.0k; Res_ohm: 33000; Value_Code: 33k0; Tolerance_%: 1; Power_W: 0.1; Value2: 0.1W; VDC_V: 75; TempCo: 100 ppm/C; U/M: EA; SizeArea_mm2: 1.28; SizeX_mm: 1.6; SizeY_mm: 0.8; AEC Category: Q200
R18 = CRCW060310K0FKEA: RES, 10.0 k, 1%, 0.1 W, 0603; Manufacturer: Vishay-Dale; CompType: Resistor; Value: 10.0k; Res_ohm: 10000; Value_Code: 10k0; Tolerance_%: 1; Power_W: 0.1; Value2: 0.1W; VDC_V: 75; TempCo: 100 ppm/C; EIA_Code: E96; U/M: EA
R19 = CRCW060310K0FKEA: RES, 10.0 k, 1%, 0.1 W, 0603; Manufacturer: Vishay-Dale; CompType: Resistor; Value: 10.0k; Res_ohm: 10000; Value_Code: 10k0; Tolerance_%: 1; Power_W: 0.1; Value2: 0.1W; VDC_V: 75; TempCo: 100 ppm/C; EIA_Code: E96; U/M: EA; AEC Category: Q200; SizeArea_mm2: 1.28; SizeX_mm: 1.6; SizeY_mm: 0.8
TP1 TP2 = 1502-2: Terminal, Turret, TH, Double; Manufacturer: Keystone; CompType: Turret Terminal; U/M: EA
U1 = TPS92692QPWPRQ1: LED Controller With Spread Spectrum Frequency Modulation and Internal PWM Generator, PWP0020D (TSSOP-20); Alternate PartNumber: TPS92692QPWPTQ1; Manufacturer: Texas Instruments; SymbolCreator: Altium; SizeArea_mm2: 41.6; SizeAreaWB_mm2: 71.4; SizeX_mm: 6.4; SizeY_mm: 6.5; SizeZ_mm: 1.2; CompType: IC; U/M: EA

## Sheet TIDA01581_2.SchDoc: Current Balance,Fault Detection, and Thermal Foldback
size 431 x 279 mm; Date: Not shown in title block; ApprovedBy: Not shown in title block; CheckedBy: Not shown in title block; Author: Not shown in title block; CompanyName: Not shown in title block; DrawnBy: Garrett Satterfield; Engineer: Not shown in title block; Organization: Not shown in title block; Address1: Not shown in title block; Address2: Not shown in title block; Address3: Not shown in title block; Address4: Not shown in title block; DocumentNumber: 1; Revision: Use project parameter SCH_Rev; SheetNumber: 2; SheetTotal: 3; PageSetup: Record=PageOptions¦CenterHorizontal=True¦CenterVertical=True¦PrintScale=1.00¦XCorrection=1.00¦YCorrection=1.00¦PrintKind=0¦BorderSize=5000000¦LeftOffset=0¦BottomOffset=0¦Orientation=2¦PaperLength=1000¦PaperWidth=1000¦Scale=100¦PaperSource=15¦PrintQuality=600¦MediaType=1¦DitherType=10¦PaperKind=Letter¦PrintScaleMode=1
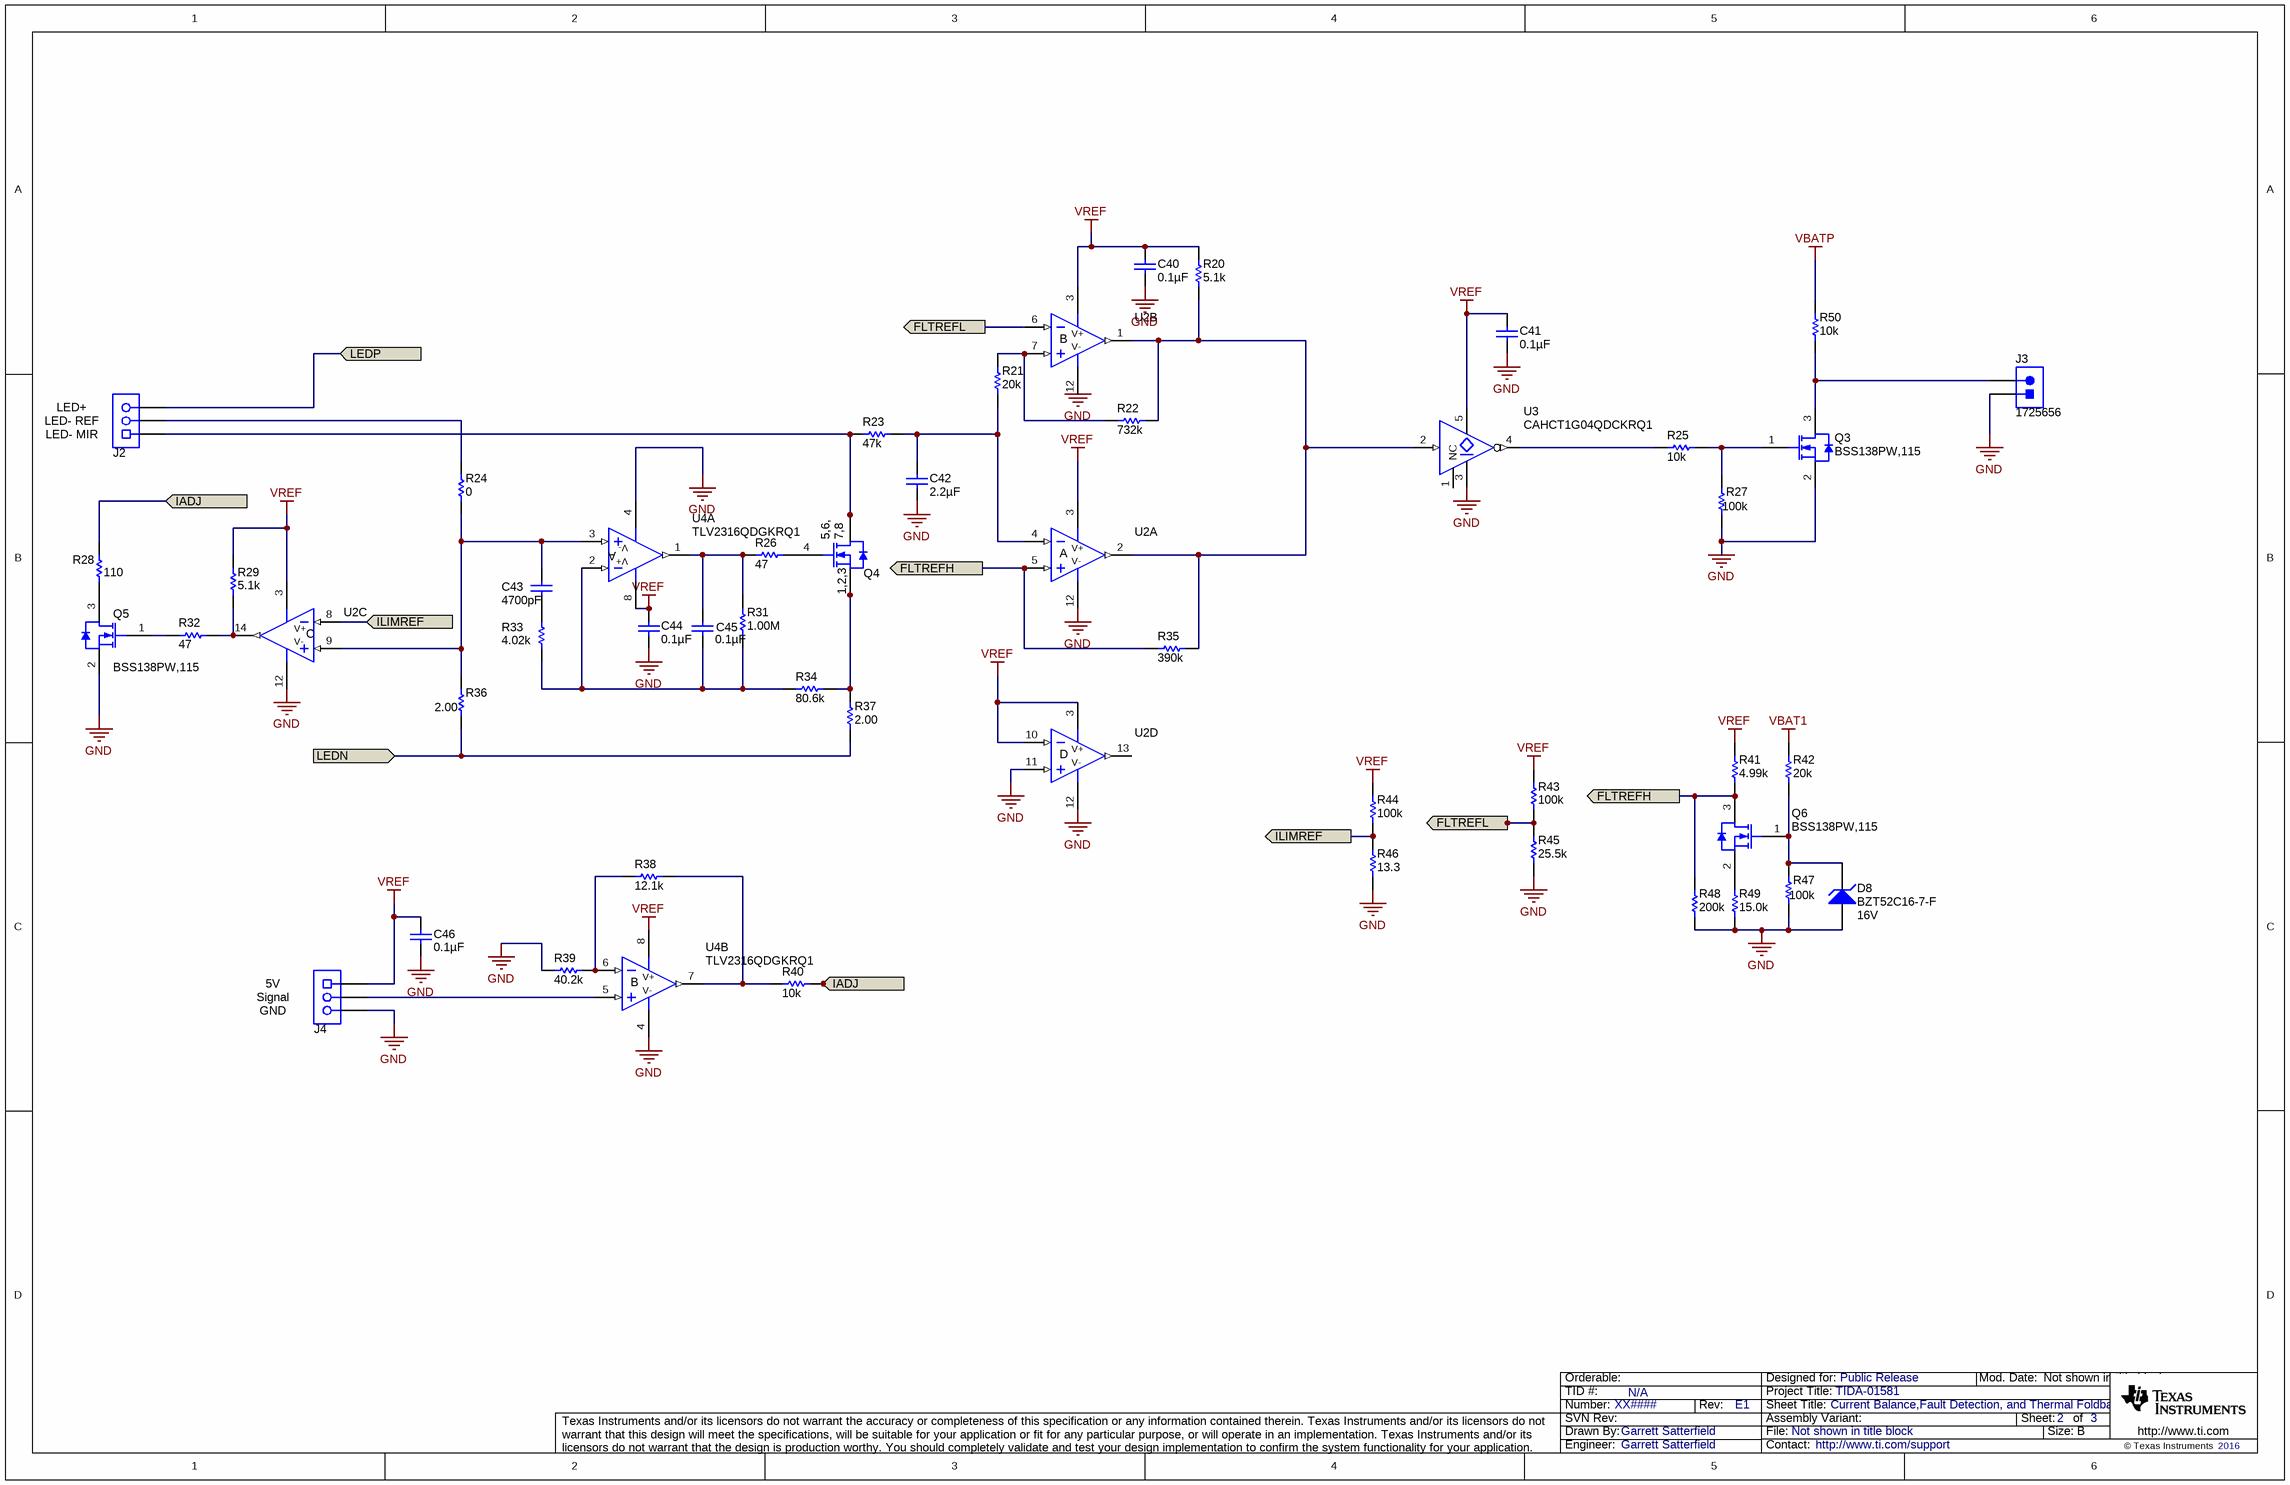
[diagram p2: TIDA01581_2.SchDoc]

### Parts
C40  ValueDisplayed: 0.1µF  [0603]  (hidden comment: 0603ZC104KAT2A)
C41  ValueDisplayed: 0.1µF  [0603]  (hidden comment: 0603ZC104KAT2A)
C42  ValueDisplayed: 2.2µF  [0603]  (hidden comment: C0603C225K8PACTU)
C43  ValueDisplayed: 4700pF  [0603]  (hidden comment: 06031C472JAT2A)
C44  ValueDisplayed: 0.1µF  [0603]  (hidden comment: 0603ZC104KAT2A)
C45  ValueDisplayed: 0.1µF  [0603]  (hidden comment: 0603ZC104KAT2A)
C46  ValueDisplayed: 0.1µF  [0603]  (hidden comment: 0603ZC104KAT2A)
D8  BZT52C16-7-F  value 16V  [SOD-123]
J2  1727023  [Phoenix_1727023]  (value not drawn)
J3  1725656  [CONN_1725656]
J4  1727023  [Phoenix_1727023]  (value not drawn)
Q3  BSS138PW,115  [SOT-323]
Q4  STL8N10LF3  [PowerFLAT5x6_R]  (value not drawn)
Q5  BSS138PW,115  [SOT-323]
Q6  BSS138PW,115  [SOT-323]
R20  ValueDisplayed: 5.1k  [0603]  (hidden comment: CRCW06035K10JNEA)
R21  ValueDisplayed: 20k  [0603]  (hidden comment: CRCW060320K0JNEA)
R22  ValueDisplayed: 732k  [0603]  (hidden comment: CRCW0603732KFKEA)
R23  ValueDisplayed: 47k  [0603]  (hidden comment: CRCW060347K0JNEA)
R24  ValueDisplayed: 0  [5108]  (hidden comment: 5108)
R25  ValueDisplayed: 10k  [0603]  (hidden comment: CRCW060310K0JNEA)
R26  ValueDisplayed: 47  [0603]  (hidden comment: CRCW060347R0JNEA)
R27  ValueDisplayed: 100k  [0603]  (hidden comment: CRCW0603100KFKEA)
R28  ValueDisplayed: 110  [0603]  (hidden comment: CRCW0603110RJNEA)
R29  ValueDisplayed: 5.1k  [0603]  (hidden comment: CRCW06035K10JNEA)
R31  ValueDisplayed: 1.00M  [0603]  (hidden comment: CRCW06031M00FKEA)
R32  ValueDisplayed: 47  [0603]  (hidden comment: CRCW060347R0JNEA)
R33  ValueDisplayed: 4.02k  [0603]  (hidden comment: CRCW06034K02FKEA)
R34  ValueDisplayed: 80.6k  [0603]  (hidden comment: CRCW060380K6FKEA)
R35  ValueDisplayed: 390k  [0603]  (hidden comment: CRCW0603390KJNEA)
R36  ValueDisplayed: 2.00  [1210M]  (hidden comment: ERJ-14BQF2R0U)
R37  ValueDisplayed: 2.00  [1210M]  (hidden comment: ERJ-14BQF2R0U)
R38  ValueDisplayed: 12.1k  [0603]  (hidden comment: CRCW060312K1FKEA)
R39  ValueDisplayed: 40.2k  [0603]  (hidden comment: CRCW060340K2FKEA)
R40  ValueDisplayed: 10k  [0603]  (hidden comment: CRCW060310K0JNEA)
R41  ValueDisplayed: 4.99k  [0603]  (hidden comment: CRCW06034K99FKEA)
R42  ValueDisplayed: 20k  [0603]  (hidden comment: CRCW060320K0JNEA)
R43  ValueDisplayed: 100k  [0603]  (hidden comment: CRCW0603100KFKEA)
R44  ValueDisplayed: 100k  [0603]  (hidden comment: CRCW0603100KFKEA)
R45  ValueDisplayed: 25.5k  [0603]  (hidden comment: CRCW060325K5FKEA)
R46  ValueDisplayed: 13.3  [0603]  (hidden comment: CRCW060313R3FKEA)
R47  ValueDisplayed: 100k  [0603]  (hidden comment: CRCW0603100KFKEA)
R48  ValueDisplayed: 200k  [0603]  (hidden comment: CRCW0603200KFKEA)
R49  ValueDisplayed: 15.0k  [0603]  (hidden comment: CRCW060315K0FKEA)
R50  ValueDisplayed: 10k  [0603]  (hidden comment: CRCW060310K0JNEA)
U2  LM2901VQPWRQ1  [PW0014A_N]  (value not drawn)  (parts A,B,C,D of 4)
U3  CAHCT1G04QDCKRQ1  [DCK0005A_N]
U4  TLV2316QDGKRQ1  [DGK0008A_N]  (parts A,B of 2)

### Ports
FLTREFH, FLTREFL, IADJ, IADJ (out), ILIMREF, LEDN (in), LEDP

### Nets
GND: C40.2 C41.2 C42.2 C44.2 C46.2 D8.2(A) J3.1 J4.3 Q3.2(S) Q5.2(S) R27.1 R39.1 R45.1 R46.1 R47.1 R48.1 R49.1 U2.11(+IN4) U2.12(V-) U3.3(GND) U4.4(V-)
VBAT1: R42.2
VBATP: R50.2
VREF: C40.1 C41.1 C44.1 C46.1 J4.1 R20.2 R29.2 R41.2 R43.2 R44.2 U2.3(V+) U2.10(-IN4) U3.5(VCC) U4.8(V+)
FLTREFH: Q6.3(D) R35.1 R41.1 R48.2 U2.5(+IN1) ; port FLTREFH
FLTREFL: R43.1 R45.2 U2.6(-IN2) ; port FLTREFL
IADJ: R28.1 R40.2 ; port IADJ
ILIMREF: R44.1 R46.2 U2.8(-IN3) ; port ILIMREF
LEDN: R36.1 R37.1 ; port LEDN
LEDP: J2.3 ; port LEDP
NetC42_1: C42.1 R21.1 R23.2 U2.4(-IN1)
NetC43_1: C43.1 R24.1 R36.2 U2.9(+IN3) U4.3(IN+)
NetC43_2: C43.2 R33.2
NetC45_1: C45.1 R26.1 R31.2 U4.1(OUT)
NetC45_2: C45.2 R31.1 R33.1 R34.1 U4.2(IN-)
NetD8_1: D8.1(K) Q6.1(G) R42.1 R47.2
NetJ2_1: J2.1 Q4.5(D) Q4.6(D) Q4.7(D) Q4.8(D) Q4.9(D) R23.1
NetJ2_2: J2.2 R24.2
NetJ3_2: J3.2 Q3.3(D) R50.1
NetJ4_2: J4.2 U4.5(IN+)
NetQ3_1: Q3.1(G) R25.2 R27.2
NetQ4_1: Q4.1(S) Q4.2(S) Q4.3(S) R34.2 R37.2
NetQ4_4: Q4.4(G) R26.2
NetQ5_1: Q5.1(G) R32.1
NetQ5_3: Q5.3(D) R28.2
NetQ6_2: Q6.2(S) R49.2
NetR20_1: R20.1 R22.2 R35.2 U2.1(OUT2) U2.2(OUT1) U3.2(A)
NetR21_2: R21.2 R22.1 U2.7(+IN2)
NetR25_1: R25.1 U3.4(Y)
NetR29_1: R29.1 R32.2 U2.14(OUT3)
NetR38_1: R38.1 R39.2 U4.6(IN-)
NetR38_2: R38.2 R40.1 U4.7(OUT)

Not connected (* = marked no-connect by the designer): U2 13(OUT4); U3 1(NC)

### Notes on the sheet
- LED+
- (near J2) LED- MIR
- (near J2) LED- REF
- 5V
- (near J4) Signal
- GND

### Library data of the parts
C40 C41 C44-C46 = 0603ZC104KAT2A: CAP, CERM, 0.1 µF, 10 V, +/- 10%, X7R, 0603; Manufacturer: AVX; Polarized: N; CompType: Capacitor; Value: 0.1uF; U/M: EA; Cap_F: 0.0000001; Tolerance_%: 10; Value1: Unknown; Value2: 10V; TaMin_C: -55; TaMax_C: 125; SizeArea_mm2: 1.28; SizeAreaWB_mm2: 4.68; SizeX_mm: 1.6; SizeY_mm: 0.8; SizeZ_mm: 1; AEC Category: Q200
C42 = C0603C225K8PACTU: CAP, CERM, 2.2 µF, 10 V, +/- 10%, X5R, 0603; Manufacturer: Kemet; Polarized: N; CompType: Capacitor; Value: 2.2uF; U/M: EA; Cap_F: 0.0000022; Tolerance_%: 10; Value1: Unknown; Value2: 10V; TaMin_C: -55; TaMax_C: 85; SizeArea_mm2: 1.28; SizeAreaWB_mm2: 4.68; SizeX_mm: 1.6; SizeY_mm: 0.8; SizeZ_mm: 1; AEC Category: Q200
C43 = 06031C472JAT2A: CAP, CERM, 4700 pF, 100 V, +/- 5%, X7R, 0603; Manufacturer: AVX; Polarized: N; CompType: Capacitor; Value: 4700pF; U/M: EA; Cap_F: 0.0000000047; Tolerance_%: 5; ESR_ohm: 0.136; Value1: 0.136 ohm; VDC_V: 100; Value2: 100V; TaMin_C: -55; TaMax_C: 125; SizeArea_mm2: 1.28; SizeAreaWB_mm2: 4.68; SizeX_mm: 1.6; SizeY_mm: 0.8; SizeZ_mm: 1; AEC Category: Q200
D8 = BZT52C16-7-F: Diode, Zener, 16 V, 500 mW, AEC-Q101, SOD-123; Manufacturer: Diodes Inc.; SymbolCreator: a0412235; U/M: EA; Power_W: 0.5; Vz_V: 16; Value1: 0.5W; RJA_CperW: 338; SizeAreaWB_mm2: 13.095; SizeArea_mm2: 6.545; SizeX_mm: 3.85; SizeY_mm: 1.7; SizeZ_mm: 1.35; AEC Category: Q101; AEC Qualified: Y
J2 J4 = 1727023: as J1 on sheet TIDA01581_1
J3 = 1725656: Terminal Block, 100mil, 2x1, 6A, 63V, TH; Manufacturer: Phoenix Contact; SymbolCreator: a0412235; U/M: EA
Q3 Q5 Q6 = BSS138PW,115: MOSFET, N-CH, 60 V, 0.32 A, AEC-Q101, SOT-323; Manufacturer: Nexperia; Alternate Manufacturer: None; U/M: EA; ChType: N; Value: 60V; VdsMax_V: 60; Value1: ? ohm; Value2: 0.72 nC; QgTyp_nC: 0.72; Vgs_V: 20; IdsMax_A: 0.32; SizeAreaWB_mm2: 10.24; SizeArea_mm2: 4.84; SizeX_mm: 2.2; SizeZ_mm: 1.1; AEC Category: Q101; AEC Qualified: Y
Q4 = STL8N10LF3: as Q2 on sheet TIDA01581_1
R20 R29 = CRCW06035K10JNEA: RES, 5.1 k, 5%, 0.1 W, 0603; Manufacturer: Vishay-Dale; CompType: Resistor; Value: 5.1k; Res_ohm: 5100; Value_Code: 5k10; Tolerance_%: 5; Power_W: 0.1; Value2: 0.1W; VDC_V: 75; TempCo: 200 ppm/C; SizeArea_mm2: 1.28; SizeX_mm: 1.6; SizeY_mm: 0.8; SizeZ_mm: 1; EIA_Code: E24; U/M: EA; AEC Category: Q200
R21 R42 = CRCW060320K0JNEA: RES, 20 k, 5%, 0.1 W, 0603; Manufacturer: Vishay-Dale; CompType: Resistor; Value: 20k; Res_ohm: 20000; Value_Code: 20k0; Tolerance_%: 5; Power_W: 0.1; Value2: 0.1W; VDC_V: 75; TempCo: 200 ppm/C; SizeArea_mm2: 1.28; SizeX_mm: 1.6; SizeY_mm: 0.8; SizeZ_mm: 1; EIA_Code: E24; U/M: EA; AEC Category: Q200
R22 = CRCW0603732KFKEA: RES, 732 k, 1%, 0.1 W, 0603; Manufacturer: Vishay-Dale; CompType: Resistor; Value: 732k; Res_ohm: 732000; Tolerance_%: 1; Power_W: 0.1; Value2: 0.1W; VDC_V: 75; TempCo: 100 ppm/C; SizeArea_mm2: 1.28; SizeX_mm: 1.6; SizeY_mm: 0.8; EIA_Code: E96; U/M: EA; AEC Category: Q200
R23 = CRCW060347K0JNEA: RES, 47 k, 5%, 0.1 W, 0603; Manufacturer: Vishay-Dale; CompType: Resistor; Value: 47k; Res_ohm: 47000; Value_Code: 47k0; Tolerance_%: 5; Power_W: 0.1; Value2: 0.1W; VDC_V: 75; TempCo: 200 ppm/C; SizeArea_mm2: 1.28; SizeX_mm: 1.6; SizeY_mm: 0.8; SizeZ_mm: 1; EIA_Code: E24; U/M: EA; AEC Category: Q200
R24 = 5108: RES, 0, 1%, 0.5 W, 1206; Manufacturer: Keystone; CompType: Resistor; Value: 0; Tolerance_%: 1; Power_W: 0.5; Value2: 0.5W; TempCo: ppm/C; SizeArea_mm2: 5.185; SizeX_mm: 3.05; SizeY_mm: 1.7; SizeZ_mm: 0.84; U/M: EA; AEC Category: Q200; AEC Qualified: N
R25 R40 R50 = CRCW060310K0JNEA: RES, 10 k, 5%, 0.1 W, 0603; Manufacturer: Vishay-Dale; CompType: Resistor; Value: 10k; Res_ohm: 10000; Value_Code: 10k0; Tolerance_%: 5; Power_W: 0.1; Value2: 0.1W; VDC_V: 75; TempCo: 200 ppm/C; SizeArea_mm2: 1.28; SizeX_mm: 1.6; SizeY_mm: 0.8; SizeZ_mm: 1; EIA_Code: E24; U/M: EA; AEC Category: Q200
R26 R32 = CRCW060347R0JNEA: RES, 47, 5%, 0.1 W, 0603; Manufacturer: Vishay-Dale; CompType: Resistor; Value: 47; Value_Code: 47R0; Tolerance_%: 5; Power_W: 0.1; Value2: 0.1W; VDC_V: 75; TempCo: 200 ppm/C; SizeArea_mm2: 1.28; SizeX_mm: 1.6; SizeY_mm: 0.8; SizeZ_mm: 1; EIA_Code: E24; U/M: EA; AEC Category: Q200
R27 R43 R44 R47 = CRCW0603100KFKEA: RES, 100 k, 1%, 0.1 W, 0603; Manufacturer: Vishay-Dale; CompType: Resistor; Value: 100k; Res_ohm: 100000; Tolerance_%: 1; Power_W: 0.1; Value2: 0.1W; VDC_V: 75; TempCo: 100 ppm/C; SizeArea_mm2: 1.28; SizeX_mm: 1.6; SizeY_mm: 0.8; EIA_Code: E96; U/M: EA; AEC Category: Q200
R28 = CRCW0603110RJNEA: RES, 110, 5%, 0.1 W, 0603; Manufacturer: Vishay-Dale; CompType: Resistor; Value: 110; Value_Code: 110R; Tolerance_%: 5; Power_W: 0.1; Value2: 0.1W; VDC_V: 75; TempCo: 200 ppm/C; SizeArea_mm2: 1.28; SizeX_mm: 1.6; SizeY_mm: 0.8; SizeZ_mm: 1; EIA_Code: E24; U/M: EA; AEC Category: Q200
R31 = CRCW06031M00FKEA: RES, 1.00 M, 1%, 0.1 W, 0603; Manufacturer: Vishay-Dale; CompType: Resistor; Value: 1.00Meg; Res_ohm: 1000000; Value_Code: 1M00; Tolerance_%: 1; Power_W: 0.1; Value2: 0.1W; VDC_V: 75; TempCo: 100 ppm/C; SizeArea_mm2: 1.28; SizeX_mm: 1.6; SizeY_mm: 0.8; EIA_Code: E96; U/M: EA; AEC Category: Q200
R33 = CRCW06034K02FKEA: RES, 4.02 k, 1%, 0.1 W, 0603; Manufacturer: Vishay-Dale; CompType: Resistor; Value: 4.02k; Res_ohm: 4020; Value_Code: 4k02; Tolerance_%: 1; Power_W: 0.1; Value2: 0.1W; VDC_V: 75; TempCo: 100 ppm/C; SizeArea_mm2: 1.28; SizeX_mm: 1.6; SizeY_mm: 0.8; EIA_Code: E96; U/M: EA; AEC Category: Q200
R34 = CRCW060380K6FKEA: RES, 80.6 k, 1%, 0.1 W, 0603; Manufacturer: Vishay-Dale; CompType: Resistor; Value: 80.6k; Res_ohm: 80600; Value_Code: 80k6; Tolerance_%: 1; Power_W: 0.1; Value2: 0.1W; VDC_V: 75; TempCo: 100 ppm/C; SizeArea_mm2: 1.28; SizeX_mm: 1.6; SizeY_mm: 0.8; EIA_Code: E96; U/M: EA; AEC Category: Q200
R35 = CRCW0603390KJNEA: RES, 390 k, 5%, 0.1 W, 0603; Manufacturer: Vishay-Dale; CompType: Resistor; Value: 390k; Res_ohm: 390000; Tolerance_%: 5; Power_W: 0.1; Value2: 0.1W; VDC_V: 75; TempCo: 200 ppm/C; SizeArea_mm2: 1.28; SizeX_mm: 1.6; SizeY_mm: 0.8; SizeZ_mm: 1; EIA_Code: E24; U/M: EA; AEC Category: Q200
R36 R37 = ERJ-14BQF2R0U: RES, 2.00, 1%, 0.5 W, AEC-Q200 Grade 0, 1210; Manufacturer: Panasonic; CompType: Resistor; Value: 2.00; Res_ohm: 2; Value_Code: 2R00; Tolerance_%: 1; Power_W: 0.5; Value2: 0.5W; TempCo: 100 ppm/C; SizeArea_mm2: 8; SizeAreaWB_mm2: 14.7; SizeX_mm: 3.2; SizeY_mm: 2.5; SizeZ_mm: 1.35; EIA_Code: E96; U/M: EA; AEC Category: Q200; AEC Qualified: Y; AEC Grade: 0
R38 = CRCW060312K1FKEA: RES, 12.1 k, 1%, 0.1 W, 0603; Manufacturer: Vishay-Dale; CompType: Resistor; Value: 12.1k; Res_ohm: 12100; Value_Code: 12k1; Tolerance_%: 1; Power_W: 0.1; Value2: 0.1W; VDC_V: 75; TempCo: 100 ppm/C; SizeArea_mm2: 1.28; SizeX_mm: 1.6; SizeY_mm: 0.8; EIA_Code: E96; U/M: EA; AEC Category: Q200
R39 = CRCW060340K2FKEA: RES, 40.2 k, 1%, 0.1 W, 0603; Manufacturer: Vishay-Dale; CompType: Resistor; Value: 40.2k; Res_ohm: 40200; Value_Code: 40k2; Tolerance_%: 1; Power_W: 0.1; Value2: 0.1W; VDC_V: 75; TempCo: 100 ppm/C; SizeArea_mm2: 1.28; SizeX_mm: 1.6; SizeY_mm: 0.8; EIA_Code: E96; U/M: EA; AEC Category: Q200
R41 = CRCW06034K99FKEA: RES, 4.99 k, 1%, 0.1 W, 0603; Manufacturer: Vishay-Dale; CompType: Resistor; Value: 4.99k; Res_ohm: 4990; Value_Code: 4k99; Tolerance_%: 1; Power_W: 0.1; Value2: 0.1W; VDC_V: 75; TempCo: 100 ppm/C; SizeArea_mm2: 1.28; SizeX_mm: 1.6; SizeY_mm: 0.8; EIA_Code: E96; U/M: EA; AEC Category: Q200
R45 = CRCW060325K5FKEA: RES, 25.5 k, 1%, 0.1 W, 0603; Manufacturer: Vishay-Dale; CompType: Resistor; Value: 25.5k; Res_ohm: 25500; Value_Code: 25k5; Tolerance_%: 1; Power_W: 0.1; Value2: 0.1W; VDC_V: 75; TempCo: 100 ppm/C; SizeArea_mm2: 1.28; SizeX_mm: 1.6; SizeY_mm: 0.8; EIA_Code: E96; U/M: EA; AEC Category: Q200
R46 = CRCW060313R3FKEA: RES, 13.3, 1%, 0.1 W, 0603; Manufacturer: Vishay-Dale; CompType: Resistor; Value: 13.3; Value_Code: 13R3; Tolerance_%: 1; Power_W: 0.1; Value2: 0.1W; VDC_V: 75; TempCo: 100 ppm/C; SizeArea_mm2: 1.28; SizeX_mm: 1.6; SizeY_mm: 0.8; EIA_Code: E96; U/M: EA; AEC Category: Q200
R48 = CRCW0603200KFKEA: RES, 200 k, 1%, 0.1 W, 0603; Manufacturer: Vishay-Dale; CompType: Resistor; Value: 200k; Res_ohm: 200000; Tolerance_%: 1; Power_W: 0.1; Value2: 0.1W; VDC_V: 75; TempCo: 100 ppm/C; SizeArea_mm2: 1.28; SizeX_mm: 1.6; SizeY_mm: 0.8; EIA_Code: E96; U/M: EA; AEC Category: Q200
R49 = CRCW060315K0FKEA: RES, 15.0 k, 1%, 0.1 W, 0603; Manufacturer: Vishay-Dale; CompType: Resistor; Value: 15.0k; Res_ohm: 15000; Value_Code: 15k0; Tolerance_%: 1; Power_W: 0.1; Value2: 0.1W; VDC_V: 75; TempCo: 100 ppm/C; SizeArea_mm2: 1.28; SizeX_mm: 1.6; SizeY_mm: 0.8; EIA_Code: E96; U/M: EA; AEC Category: Q200
U2 = LM2901VQPWRQ1: Automotive Quad Comparator, PW0014A; Manufacturer: Texas Instruments; SymbolCreator: Altium; CompType: OpAmp IC
U3 = CAHCT1G04QDCKRQ1: Single Inverter Gate, DCK0005A (SOT-SC70-5); Manufacturer: Texas Instruments; SymbolCreator: a0411947; SizeArea_mm2: 4.2; SizeAreaWB_mm2: 9.3; SizeX_mm: 2.1; SizeY_mm: 2; SizeZ_mm: 1.1; CompType: IC; U/M: EA
U4 = TLV2316QDGKRQ1: 10-MHz, Rail-to-Rail Input/Output, Low-Voltage, 1.8-V CMOS Operational Amplifier, DGK0008A (VSSOP-8); Alternate PartNumber: TLV2316QDGKTQ1; Manufacturer: Texas Instruments; CompType: IC; SizeArea_mm2: 15.655; SizeAreaWB_mm2: 35.955; SizeX_mm: 5.05; SizeY_mm: 3.1; SizeZ_mm: 1.1; U/M: EA

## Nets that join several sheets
GND: TIDA01581_1 (45 pins), TIDA01581_2 (21 pins)
VBAT1: TIDA01581_1 (5 pins), TIDA01581_2 (R42.2)
VBATP: TIDA01581_1 (6 pins), TIDA01581_2 (R50.2)
VREF: TIDA01581_1 (C29.2 R16.1 U1.2), TIDA01581_2 (14 pins)
IADJ: TIDA01581_1 (R13.1), TIDA01581_2 (R28.1 R40.2)
LEDN: TIDA01581_1 (C16.1 C17.2 L7.2), TIDA01581_2 (R36.1 R37.1)
LEDP: TIDA01581_1 (C16.2 C17.1 L5.2), TIDA01581_2 (J2.3)

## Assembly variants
001: not fitted C22 FID1 FID2 FID3 R11
Only Populated: not fitted C1 C5 C13 C14 C17 C24 C41 C42 C45 D5 D8 J3 Q3 Q6 R1 R3 R17 R20 R21 R22 R23 R25 R27 R27 R35 R41 R42 R43 R45 R47 R48 R49 R50 U3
